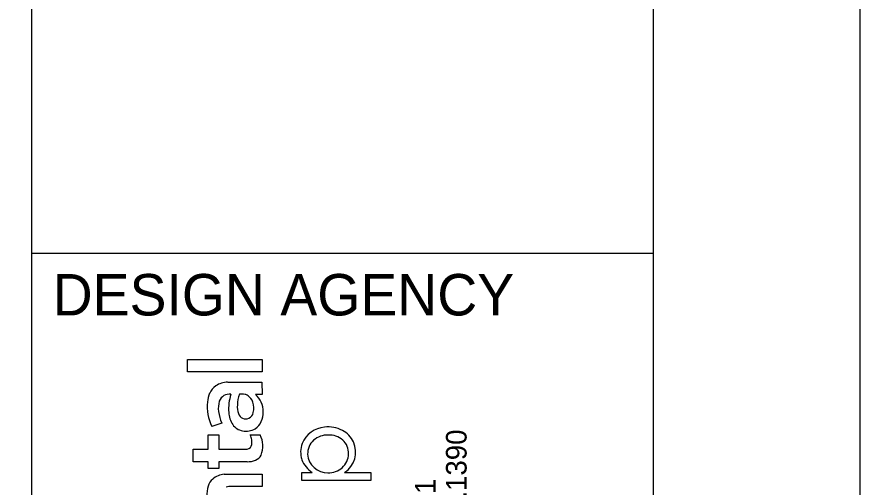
# Model space of a CAD drawing. Extents: x 0 to 70.6, y 0 to 31.9.
# Drawn here: x 31.964 to 34, y 4.436 to 5.57 of the extents above; entities that cross this region are included whole.
import ezdxf

# ---------------------------------------------------------------- set-up
doc = ezdxf.new("R2010")
doc.units = 0
for name, color, linetype in [('GM_X_County', 7, 'Continuous'), ('GM_X_Section', 7, 'Continuous'), ('GM_X_Township', 7, 'Continuous')]:
    doc.layers.add(name, color=color, linetype=linetype)

msp = doc.modelspace()

# ---------------------------------------------------------------- linework, layer by layer
at = {"layer": 'GM_X_County'}
for p, q in [((32, 0.5), (32, 21.5)), ((32, 5), (33.5, 5))]:
    msp.add_line(p, q, dxfattribs=at)
msp.add_lwpolyline([(1.5, 21.5), (33.5, 21.5), (33.5, 0.5), (1.5, 0.5)], close=True, dxfattribs=at)
at = {"layer": 'GM_X_Section'}
msp.add_lwpolyline([(0, 0), (34, 0), (34, 22), (0, 22)], close=True, dxfattribs=at)
at = {"layer": 'GM_X_Township'}
for p, q in [((32.3756, 4.7141), (32.3756, 4.744)), ((32.3756, 4.744), (32.5557, 4.744)), ((32.5557, 4.744), (32.5557, 4.7141)), ((32.5557, 4.7141), (32.3756, 4.7141)), ((32.4727, 4.689), (32.5555, 4.6892)), ((32.5555, 4.6892), (32.5557, 4.6596)), ((32.5557, 4.6596), (32.5397, 4.6596)), ((32.4582, 4.5904), (32.4343, 4.5823)), ((32.4254, 4.527), (32.4255, 4.5621)), ((32.4255, 4.5621), (32.4511, 4.5621)), ((32.4511, 4.5621), (32.4512, 4.527)), ((32.527, 4.5616), (32.5511, 4.5616)), ((32.3896, 4.4972), (32.3896, 4.527)), ((32.3896, 4.527), (32.4254, 4.527)), ((32.4512, 4.527), (32.515, 4.527)), ((32.515, 4.527), (32.52, 4.5275)), ((32.4254, 4.4972), (32.3896, 4.4972)), ((32.4254, 4.4807), (32.4254, 4.4972)), ((32.4511, 4.4807), (32.4254, 4.4807)), ((32.5197, 4.4972), (32.4511, 4.4972)), ((32.4511, 4.4972), (32.4511, 4.4807)), ((32.4644, 4.4669), (32.4729, 4.4673)), ((32.4729, 4.4673), (32.5557, 4.4673)), ((32.5557, 4.4673), (32.5557, 4.4375)), ((32.6515, 4.4521), (32.6515, 4.4711)), ((32.6515, 4.4711), (32.6771, 4.4711)), ((32.7549, 4.4713), (32.8186, 4.4711)), ((32.8186, 4.4711), (32.8184, 4.4521)), ((32.8184, 4.4521), (32.6515, 4.4521)), ((32.5557, 4.4375), (32.4814, 4.4375))]:
    msp.add_line(p, q, dxfattribs=at)
msp.add_lwpolyline([(32.3756, 4.7141), (32.3756, 4.744), (32.5557, 4.744), (32.5557, 4.7141)], close=True, dxfattribs=at)
for points in [[(32.4727, 4.689), (32.5555, 4.6892), (32.5557, 4.6596)], [(32.5557, 4.6596), (32.5397, 4.6596)], [(32.4582, 4.5904), (32.4343, 4.5823)], [(32.5197, 4.4972), (32.4511, 4.4972), (32.4511, 4.4807), (32.4254, 4.4807), (32.4254, 4.4972), (32.3896, 4.4972), (32.3896, 4.527), (32.4254, 4.527), (32.4255, 4.5621), (32.4511, 4.5621), (32.4512, 4.527), (32.515, 4.527), (32.52, 4.5275)], [(32.527, 4.5616), (32.5511, 4.5616)], [(32.4644, 4.4669), (32.4729, 4.4673), (32.5557, 4.4673), (32.5557, 4.4375), (32.4814, 4.4375)], [(32.7549, 4.4713), (32.8186, 4.4711), (32.8184, 4.4521), (32.6515, 4.4521)], [(32.6515, 4.4521), (32.6515, 4.4711), (32.6771, 4.4711)]]:
    msp.add_lwpolyline(points, dxfattribs=at)
for centre, radius, start, end in [((32.4745, 4.6326), 0.0565, 91.8942, 122.6317), ((32.4745, 4.6326), 0.0565, 91.8942, 122.6317), ((32.4685, 4.6447), 0.043, 124.537, 155.6594), ((32.4685, 4.6447), 0.043, 124.537, 155.6594), ((32.4882, 4.6361), 0.0646, 155.9764, 175.3149), ((32.4882, 4.6361), 0.0646, 155.9764, 175.3149), ((32.5076, 4.6265), 0.0576, 163.1369, 188.1675), ((32.5076, 4.6265), 0.0576, 163.1369, 188.1675), ((32.4753, 4.6356), 0.024, 119.4252, 161.6629), ((32.4753, 4.6356), 0.024, 119.4252, 161.6629), ((32.4779, 4.6278), 0.0321, 85.3802, 116.6222), ((32.4779, 4.6278), 0.0321, 85.3802, 116.6222), ((32.5879, 4.6251), 0.1129, 162.0821, 184.5285), ((32.5879, 4.6251), 0.1129, 162.0821, 184.5285), ((32.5801, 4.6313), 0.0841, 159.8366, 178.0362), ((32.5801, 4.6313), 0.0841, 159.8366, 178.0362), ((32.5051, 4.6074), 0.053, 79.6696, 94.2322), ((32.5051, 4.6074), 0.053, 79.6696, 94.2322), ((32.5089, 4.6364), 0.0238, 56.8913, 76.2149), ((32.5089, 4.6364), 0.0238, 56.8913, 76.2149), ((32.5052, 4.6318), 0.0297, 17.5984, 55.7282), ((32.5052, 4.6318), 0.0297, 17.5984, 55.7282), ((32.5055, 4.6191), 0.0529, 358.0746, 49.762), ((32.5055, 4.6191), 0.0529, 358.0746, 49.762), ((32.5364, 4.6308), 0.113, 174.6101, 205.3899), ((32.5364, 4.6308), 0.113, 174.6101, 205.3899), ((32.5466, 4.6303), 0.0506, 175.5903, 199.8857), ((32.5466, 4.6303), 0.0506, 175.5903, 199.8857), ((32.4916, 4.6264), 0.0443, 345.9408, 18.9919), ((32.4916, 4.6264), 0.0443, 345.9408, 18.9919), ((32.5473, 4.6297), 0.0973, 186.7598, 203.7981), ((32.5473, 4.6297), 0.0973, 186.7598, 203.7981), ((32.5328, 4.6187), 0.0575, 182.5676, 213.7144), ((32.5328, 4.6187), 0.0575, 182.5676, 213.7144), ((32.5164, 4.6189), 0.0184, 198.2844, 293.3081), ((32.5164, 4.6189), 0.0184, 198.2844, 293.3081), ((32.5152, 4.6199), 0.0199, 295.2883, 347.4639), ((32.5152, 4.6199), 0.0199, 295.2883, 347.4639), ((32.5019, 4.6168), 0.0566, 336.016, 0.5951), ((32.5019, 4.6168), 0.0566, 336.016, 0.5951), ((32.5149, 4.6078), 0.0366, 215.0668, 259.8133), ((32.5149, 4.6078), 0.0366, 215.0668, 259.8133), ((32.5175, 4.6097), 0.0394, 303.4436, 336.18), ((32.5175, 4.6097), 0.0394, 303.4436, 336.18), ((32.5175, 4.6131), 0.0423, 257.5256, 300.882), ((32.5175, 4.6131), 0.0423, 257.5256, 300.882), ((32.4863, 4.542), 0.0452, 10.1545, 25.723), ((32.4863, 4.542), 0.0452, 10.1545, 25.723), ((32.503, 4.5351), 0.0549, 336.589, 28.8991), ((32.503, 4.5351), 0.0549, 336.589, 28.8991), ((32.7108, 4.5182), 0.0624, 93.9866, 158.3119), ((32.7108, 4.5182), 0.0624, 93.9866, 158.3119), ((32.7138, 4.5102), 0.0513, 87.8965, 131.1812), ((32.7138, 4.5102), 0.0513, 87.8965, 131.1812), ((32.7156, 4.5065), 0.0746, 62.6889, 97.0135), ((32.7156, 4.5065), 0.0746, 62.6889, 97.0135), ((32.7175, 4.5102), 0.0513, 49.9089, 92.0363), ((32.7175, 4.5102), 0.0513, 49.9089, 92.0363), ((32.7212, 4.5191), 0.0608, 25.0657, 61.9602), ((32.7212, 4.5191), 0.0608, 25.0657, 61.9602), ((32.4957, 4.5436), 0.0356, 351.914, 10.2059), ((32.4957, 4.5436), 0.0356, 351.914, 10.2059), ((32.707, 4.5202), 0.0581, 158.656, 198.171), ((32.707, 4.5202), 0.0581, 158.656, 198.171), ((32.7092, 4.5167), 0.0434, 132.3289, 182.0949), ((32.7092, 4.5167), 0.0434, 132.3289, 182.0949), ((32.7215, 4.5173), 0.0433, 358.0487, 47.9447), ((32.7215, 4.5173), 0.0433, 358.0487, 47.9447), ((32.7245, 4.52), 0.0574, 301.9776, 25.6418), ((32.7245, 4.52), 0.0574, 301.9776, 25.6418), ((32.5184, 4.54), 0.0126, 277.6142, 353.7918), ((32.5184, 4.54), 0.0126, 277.6142, 353.7918), ((32.5209, 4.5486), 0.0514, 268.6727, 291.5235), ((32.5209, 4.5486), 0.0514, 268.6727, 291.5235), ((32.5291, 4.5261), 0.0275, 292.6889, 332.0598), ((32.5291, 4.5261), 0.0275, 292.6889, 332.0598), ((32.7103, 4.5243), 0.0627, 200.8399, 238.0162), ((32.7103, 4.5243), 0.0627, 200.8399, 238.0162), ((32.7135, 4.5181), 0.0478, 183.5974, 271.7045), ((32.7135, 4.5181), 0.0478, 183.5974, 271.7045), ((32.7172, 4.518), 0.0477, 267.3149, 357.4019), ((32.7172, 4.518), 0.0477, 267.3149, 357.4019), ((32.4687, 4.4172), 0.0499, 94.9706, 130.2248), ((32.4687, 4.4172), 0.0499, 94.9706, 130.2248), ((32.4635, 4.4255), 0.0402, 132.2238, 161.6823), ((32.4635, 4.4255), 0.0402, 132.2238, 161.6823), ((32.4787, 4.4211), 0.056, 162.274, 187.7917), ((32.4787, 4.4211), 0.056, 162.274, 187.7917), ((32.4811, 4.3915), 0.046, 89.6051, 105.3303), ((32.4811, 4.3915), 0.046, 89.6051, 105.3303)]:
    msp.add_arc(centre, radius, start, end, dxfattribs=at)

# ---------------------------------------------------------------- texts
msp.add_text('DESIGN AGENCY', height=0.1, dxfattribs=at).set_placement((32.05, 4.85))
for s, p in [('800.835.1390', (33.0497, 4.1671)), ('450 GRANT ST., AKRON, OH  44311', (32.9749, 3.3374))]:
    msp.add_text(s, height=0.049846, rotation=90, dxfattribs=at).set_placement(p)

doc.saveas('drawing.dxf')
